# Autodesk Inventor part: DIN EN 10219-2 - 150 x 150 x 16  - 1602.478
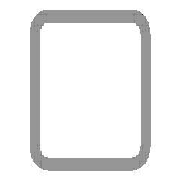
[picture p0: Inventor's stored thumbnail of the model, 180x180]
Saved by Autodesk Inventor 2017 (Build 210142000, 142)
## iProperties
Created: 2017-11
Part Number: DIN EN 10219-2 - 150 x 150 x 16  - 1602.478
Material: Steel, Mild
Description: Cold formed welded structural hollow sections of non-alloy and fine grain structural steel
Document SubType Name: Modeling
Standard: DIN
Designer: iusti
Standard Revision: 2006-07
Standards Organization: DIN
Language: en-US
Size Designation: 150 x 150 x 16
Categories: <MemberInstance><Categories><Category DisplayName="Structural Shapes" InternalName="089c4875-fa83-4c05-b084-43b9cc11f5ed" Mnemonic="GRDR"><CategoryParameter Dis
Stock Number: 150 x 150 x 16
Mass: 88044.5 g
Surface Area: 14205.2 cm^2
Volume: 11215.9 cm^3
Density: 7.85 g/cm^3
Appearance: Semi-Polished
IsCustomPart: 1
G_W: 150.000 mm
G_H: 150.000 mm
G_L: 1602.478 mm
+346FD258-9F9C-4BDE-884E-4FE9BE76FCEA+CUTDETAIL2: Miter 69.88 deg
+B95BDB02-C4C2-4ECB-9363-19BA39C44CCB+CUTDETAIL3: Miter 45.00 deg
_CCFamilyMember: 76
_CCFamilyDisplayName: DIN EN 10219-2 (Square Hollow Section - Cold Formed) - Cold formed welded structural hollow sections of non-alloy and fine grain structural steel
_FrameMemberDoc: Frame Member File
_Version: 15.0.0
_GetPNFromCC: 1
Author: iusti
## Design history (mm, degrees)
node "Start plane"
node "End plane"
sketch "Sketch"
  geometry: L1 (-75, -27)-(-75, 27); L2 (-27, 75)-(27, 75); L3 (75, 27)-(75, -27); L4 (27, -75)-(-27, -75); L5 (-27, 59)-(27, 59); L6 (59, 27)-(59, -27); L7 (27, -59)-(-27, -59); L8 (-59, -27)-(-59, 27); L9 (0, 118.918)-(0, -118.918) reference; L10 (-118.918, 0)-(118.918, 0) reference; A1 r 48 centre (-27, -27) between (-75, -27) and (-27, -75); A2 r 48 centre (-27, 27) between (-27, 75) and (-75, 27); A3 r 48 centre (27, 27) between (75, 27) and (27, 75); A4 r 48 centre (27, -27) between (27, -75) and (75, -27); A5 r 32 centre (-27, 27) between (-27, 59) and (-59, 27); A6 r 32 centre (27, 27) between (59, 27) and (27, 59); A7 r 32 centre (27, -27) between (27, -59) and (59, -27); A8 r 32 centre (-27, -27) between (-59, -27) and (-27, -59)
  constraints: 16 end point, 16 point on circle, 8 centre point, 8 tangent, 4 parallel, 3 equal radius, 2 perpendicular, 7 other
  dimensions: "d7" = 48 radius of A1 (= G_IR); "d10" = 150 distance between parallel lines of L2 L4 (= G_H); "d11" = 150 distance between parallel lines of L1 L3 (= G_W); "d12" = 16 distance between parallel lines of L3 L6 (= G_T); "d15" = 75 distance between parallel lines of L2 L10 (= 0.5 x d10); "d16" = 75 distance between parallel lines of L9 L3 (= 0.5 x d11)
extrude "Body" new body sketch "Sketch" stored distance "d3" = 1602.4779 (= G_L); taper "d4" = 0 deg
node "Driven Length"
  sketch "Sketch3"
    geometry: L1 (0, 0)-(10, 0) reference
    constraints: 2 end point, 1 horizontal
  workplane "Work Plane3"
  sketch "Sketch4"
    geometry: L1 (-2, -75)-(12, -75) reference; L2 (-2, 1527.478)-(12, 1527.478) reference
    dimensions: "d18" = 1602.4779 distance between parallel lines of L1 L2 (derived)
workplane "Work Plane5"
split "Split2"
workplane "Work Plane6"
split "Split3"
body "Solid1"
other parameters: "G_W" = 150 [user parameter; used in 1 equation term], "G_H" = 150 [user parameter; used in 1 equation term], "G_T" = 16 [user parameter; used in 1 equation term], "G_IR" = 48 [user parameter; used in 1 equation term], "G_L" = 1602.4779 (= d18) [user parameter; used in 1 equation term], "G_OFFSET_START" = 75 [user parameter; used in 1 equation term], "G_OFFSET_END" = 27.4779 [user parameter; used in 1 equation term], "d13" = -75 (= -G_OFFSET_START), "d14" = 1527.4779 (= G_OFFSET_END + B_L), "d17" = 90 deg
